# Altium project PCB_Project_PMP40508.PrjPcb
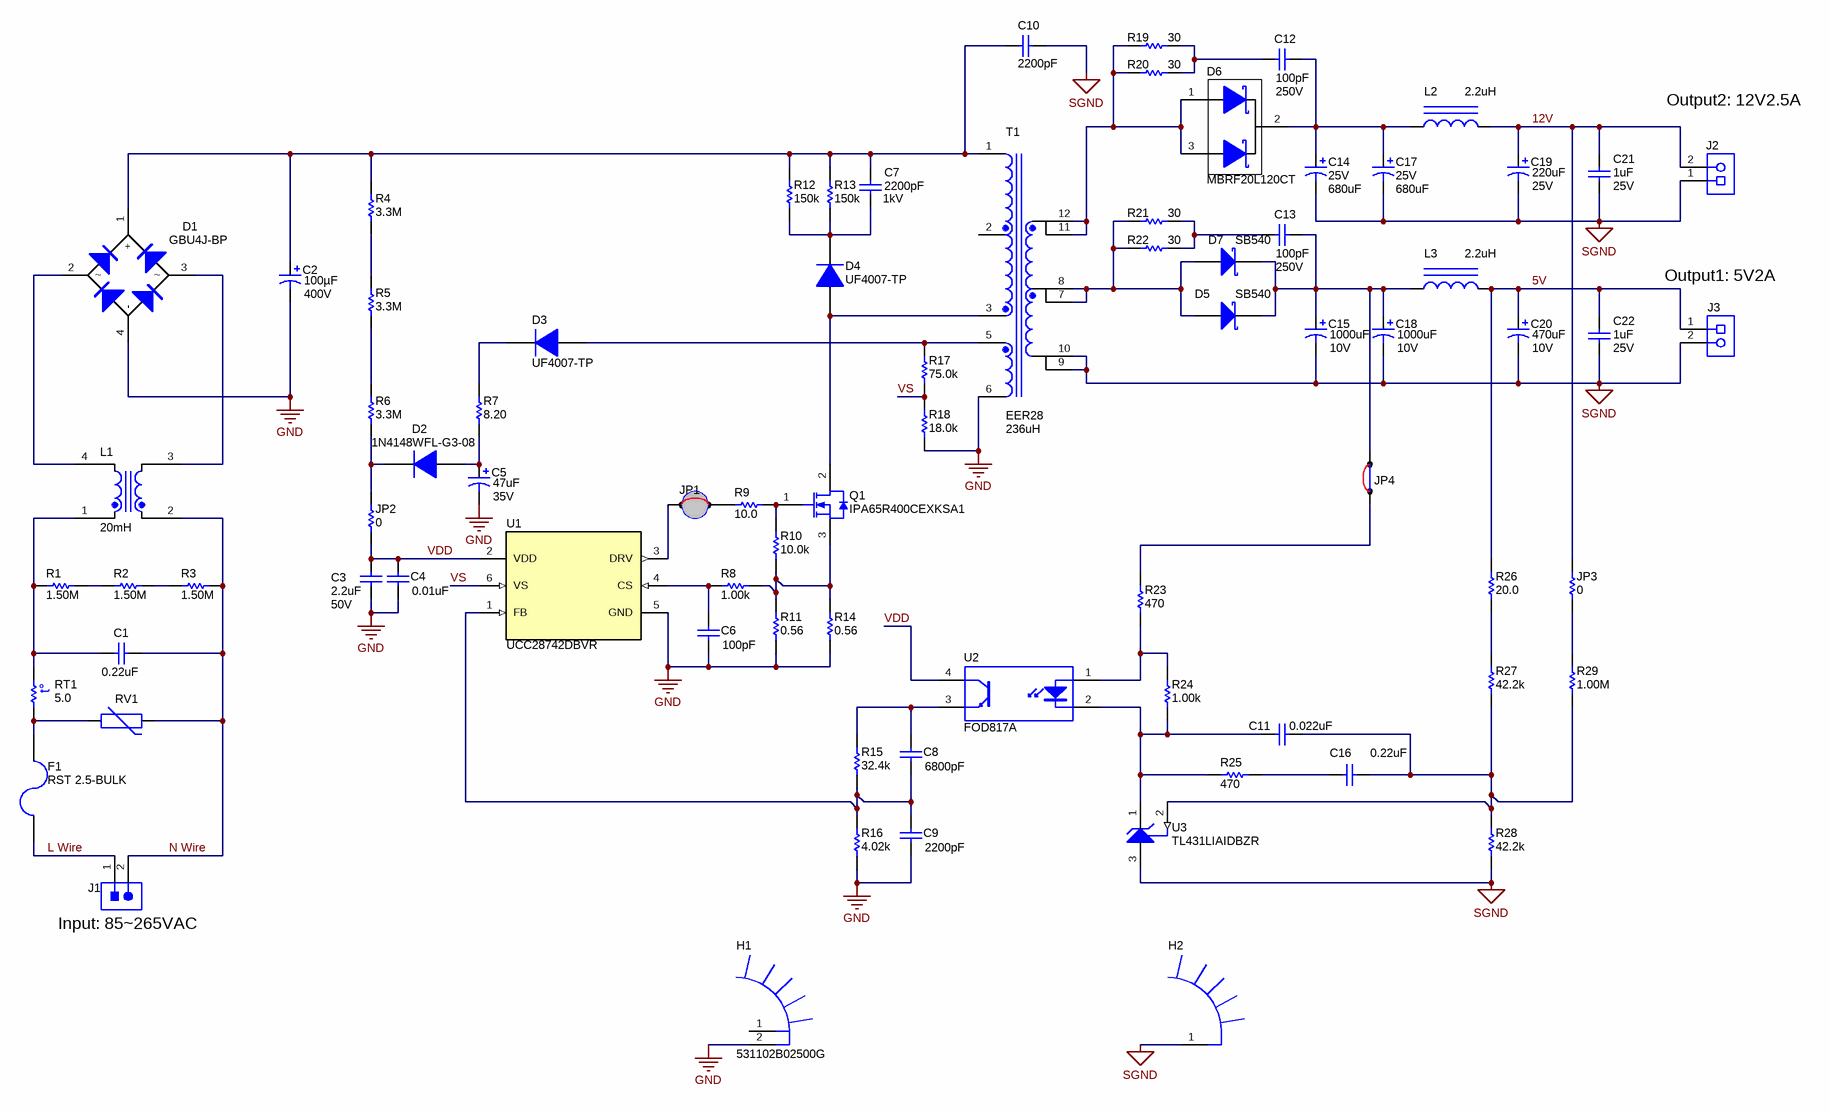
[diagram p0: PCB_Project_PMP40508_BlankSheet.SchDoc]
TID: N/A; TechSupport: http://www.ti.com/support; SCH_Rev: E1; PRJ_Title: AC input, 5V/2A and 12V/2.5A Flyback Converter; PRJ_Number: PMP40508; PRJ_Engineer: San Chen; PRJ_Customer: Public Release; PCB_Rev: E1; PCB_Layout: San Chen; CopyrightYear: 2018
1 sheet, 78 parts. Net scope: global (net labels, ports and power ports of the same name join across sheets).
Board file: PCB_Project_PMP40508_PCB.PcbDoc

## Sheet PCB_Project_PMP40508_BlankSheet.SchDoc
size 431 x 279 mm; Date: Not shown in title block; ApprovedBy: Not shown in title block; CheckedBy: Not shown in title block; Author: Not shown in title block; CompanyName: Not shown in title block; DrawnBy: San Chen; Engineer: Not shown in title block; Organization: Not shown in title block; Address1: Not shown in title block; Address2: Not shown in title block; Address3: Not shown in title block; Address4: Not shown in title block; DocumentNumber: 1; Revision: Use project parameter SCH_Rev; SheetNumber: 1; SheetTotal: 1; PageSetup: Record=PageOptions¦CenterHorizontal=True¦CenterVertical=True¦PrintScale=1.00¦XCorrection=1.00¦YCorrection=1.00¦PrintKind=0¦BorderSize=5000000¦LeftOffset=0¦BottomOffset=0¦Orientation=2¦PaperLength=1000¦PaperWidth=1000¦Scale=100¦PaperSource=15¦PrintQuality=600¦MediaType=1¦DitherType=10¦PaperKind=Letter¦PrintScaleMode=1

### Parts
C1  ValueDisplayed: 0.22uF  [WCAP-FTX2_1800x600x1150]  (hidden comment: 890324025027CS)
C2  VDC_V: 400V  ValueDisplayed: 100µF  [Chemi-Con_1800x3150]  (hidden comment: EKXG401ELL101MMN3S)
C3  VDC_V: 50V  ValueDisplayed: 2.2uF  [0805_HV]  (hidden comment: C2012X7R1H225K125AC)
C4  ValueDisplayed: 0.01uF  [0603]  (hidden comment: GRM188R71H103KA01D)
C5  VDC_V: 35V  ValueDisplayed: 47uF  [Chemi-Con_500x1100]  (hidden comment: EKMG350ELL470ME11D)
C6  ValueDisplayed: 100pF  [0603]  (hidden comment: CL10B101KB8NNNC)
C7  VDC_V: 1kV  ValueDisplayed: 2200pF  [CK45_850x500x1250]  (hidden comment: CK45-B3AD222KYNNA)
C8  ValueDisplayed: 6800pF  [0603]  (hidden comment: GRM188R71H682KA01D)
C9  ValueDisplayed: 2200pF  [0603]  (hidden comment: GRM188R71H222KA01D)
C10  ValueDisplayed: 2200pF  [C900_9x13]  (hidden comment: C921U222MVVDBA7317)
C11  ValueDisplayed: 0.022uF  [0603]  (hidden comment: GRM188R71H223KA01D)
C12  VDC_V: 250V  ValueDisplayed: 100pF  [0805_HV]  (hidden comment: GRM21A5C2E101JW01D)
C13  VDC_V: 250V  ValueDisplayed: 100pF  [0805_HV]  (hidden comment: GRM21A5C2E101JW01D)
C14  VDC_V: 25V  ValueDisplayed: 680uF  [Chemi-Con_1000x2000]  (hidden comment: EKZE250ELL681MJ20S)
C15  VDC_V: 10V  ValueDisplayed: 1000uF  [Chemi-Con_1000x1600]  (hidden comment: EKZE100ELL102MJ16S)
C16  ValueDisplayed: 0.22uF  [0603]  (hidden comment: GRM188R71E224KA88D)
C17  VDC_V: 25V  ValueDisplayed: 680uF  [Chemi-Con_1000x2000]  (hidden comment: EKZE250ELL681MJ20S)
C18  VDC_V: 10V  ValueDisplayed: 1000uF  [Chemi-Con_1000x1600]  (hidden comment: EKZE100ELL102MJ16S)
C19  VDC_V: 25V  ValueDisplayed: 220uF  [Chemi-Con_800x1150]  (hidden comment: EKZE250ELL221MHB5D)
C20  VDC_V: 10V  ValueDisplayed: 470uF  [Chemi-Con_800x1150]  (hidden comment: EKZE100ELL471MHB5D)
C21  VDC_V: 25V  ValueDisplayed: 1uF  [0805_HV]  (hidden comment: GRM216R61E105KA12D)
C22  VDC_V: 25V  ValueDisplayed: 1uF  [0805_HV]  (hidden comment: GRM216R61E105KA12D)
D1  GBU4J-BP  [GBU]
D2  1N4148WFL-G3-08  [SOD-123FL]
D3  UF4007-TP  [DO-41]
D4  UF4007-TP  [DO-41]
D5  SB540  [DO-201AD_Vert]
D6  MBRF20L120CT  [TO-220AB]
D7  SB540  [DO-201AD_Vert]
F1  RST 2.5-BULK  [FUSE_RST]
H1  531102B02500G  [531102]
H2  (no value)  [PCBComponent_1]
J1  1-1318301-2  [Amp_1-1318301-2]  (value not drawn)
J2  691214110002  [Wurth_691214110002]  (value not drawn)
J3  691214110002  [Wurth_691214110002]  (value not drawn)
JP1  923345-02-C  [923345-02-C]  (value not drawn)
JP2  ValueDisplayed: 0  [1206]  (hidden comment: RC1206JR-070RL)
JP3  ValueDisplayed: 0  [1206]  (hidden comment: RC1206JR-070RL)
JP4  923345-02-C  [923345-02-C]  (value not drawn)
L1  value 20mH  [WE-CMB_M]  (hidden comment: 744823220)
L2  ValueDisplayed: 2.2uH  [WE-TI_5075]  (hidden comment: 7447462022)
L3  ValueDisplayed: 2.2uH  [WE-TI_5075]  (hidden comment: 7447462022)
Q1  IPA65R400CEXKSA1  [TO-220FP]
R1  ValueDisplayed: 1.50M  [1206]  (hidden comment: RC1206FR-071M5L)
R2  ValueDisplayed: 1.50M  [1206]  (hidden comment: RC1206FR-071M5L)
R3  ValueDisplayed: 1.50M  [1206]  (hidden comment: RC1206FR-071M5L)
R4  ValueDisplayed: 3.3M  [1206]  (hidden comment: CRCW12063M30JNEA)
R5  ValueDisplayed: 3.3M  [1206]  (hidden comment: CRCW12063M30JNEA)
R6  ValueDisplayed: 3.3M  [1206]  (hidden comment: CRCW12063M30JNEA)
R7  ValueDisplayed: 8.20  [1206]  (hidden comment: RC1206FR-078R2L)
R8  ValueDisplayed: 1.00k  [0603]  (hidden comment: RC0603FR-071KL)
R9  ValueDisplayed: 10.0  [1206]  (hidden comment: RC1206FR-0710RL)
R10  ValueDisplayed: 10.0k  [0603]  (hidden comment: RC0603FR-0710KL)
R11  ValueDisplayed: 0.56  [1206]  (hidden comment: ERJ-8RQFR56V)
R12  ValueDisplayed: 150k  [PR01]  (hidden comment: PR01000101503JR500)
R13  ValueDisplayed: 150k  [PR01]  (hidden comment: PR01000101503JR500)
R14  ValueDisplayed: 0.56  [1206]  (hidden comment: ERJ-8RQFR56V)
R15  ValueDisplayed: 32.4k  [0603]  (hidden comment: RC0603FR-0732K4L)
R16  ValueDisplayed: 4.02k  [0603]  (hidden comment: RC0603FR-074K02L)
R17  ValueDisplayed: 75.0k  [0805_HV]  (hidden comment: ERJ-6ENF7502V)
R18  ValueDisplayed: 18.0k  [0603]  (hidden comment: RC0603FR-0718KL)
R19  ValueDisplayed: 30  [1206]  (hidden comment: CRCW120630R0JNEA)
R20  ValueDisplayed: 30  [1206]  (hidden comment: CRCW120630R0JNEA)
R21  ValueDisplayed: 30  [1206]  (hidden comment: CRCW120630R0JNEA)
R22  ValueDisplayed: 30  [1206]  (hidden comment: CRCW120630R0JNEA)
R23  ValueDisplayed: 470  [0603]  (hidden comment: RC0603FR-07470RL)
R24  ValueDisplayed: 1.00k  [0603]  (hidden comment: RC0603FR-071KL)
R25  ValueDisplayed: 470  [0603]  (hidden comment: RC0603FR-07470RL)
R26  ValueDisplayed: 20.0  [0603]  (hidden comment: RC0603FR-0720RL)
R27  ValueDisplayed: 42.2k  [0603]  (hidden comment: RC0603FR-0742K2L)
R28  ValueDisplayed: 42.2k  [0603]  (hidden comment: RC0603FR-0742K2L)
R29  ValueDisplayed: 1.00M  [0603]  (hidden comment: RC0603FR-071ML)
RT1  value 5.0  [S235]  (hidden comment: B57235S0509M000)
RV1  B72210S2271K101  [TDK_B72210S2271K101]  (value not drawn)
T1  value 236uH  ValueDisplayed: EER28  [PCBComponent_1]  (hidden comment: YXS60989T)
U1  UCC28742DBVR  [DBV0006A_N]
U2  FOD817A  [DIP-4]
U3  TL431LIAIDBZR  [DBZ0003A_N]

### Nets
GND: C2.2(-) C3.2 C4.2 C5.2(-) C6.2 C9.2 D1.4(-) H1.2 R11.1 R14.1 R16.1 R18.1 T1.6 U1.5(GND)
SGND: C10.1 C14.2(-) C15.2(-) C17.2(-) C18.2(-) C19.2(-) C20.2(-) C21.2 C22.2 H2.1 J2.1 J3.2 R28.1 T1.9 T1.10 U3.3(ANODE)
5V: C20.1(+) C22.1 J3.1 L3.2 R26.2
12V: C19.1(+) C21.1 J2.2 JP3.2 L2.2
L Wire: F1.2 J1.1
N Wire: C1.1 J1.2 L1.2 R3.2 RV1.2
VDD: C3.1 C4.1 JP2.1 U1.2(VDD) U2.4(C)
VS: R17.1 R18.2 U1.6(VS)
NetC1_2: C1.2 L1.1 R1.1 RT1.2
NetC2_1: C2.1(+) C7.1 C10.2 D1.1(+) R4.2 R12.1 R13.1 T1.1
NetC5_1: C5.1(+) D2.2(A) R7.1
NetC6_1: C6.1 R8.1 U1.4(CS)
NetC7_2: C7.2 D4.1(K) R12.2 R13.2
NetC8_1: C8.1 R15.2 U2.3(E)
NetC8_2: C8.2 C9.1 R15.1 R16.2 U1.1(FB)
NetC11_1: C11.1 C16.1 R27.1 R28.2 R29.1 U3.2(REF)
NetC11_2: C11.2 R24.1 R25.2 U2.2(K) U3.1(CATHODE)
NetC12_1: C12.1 C14.1(+) C17.1(+) D6.2(K) L2.1
NetC12_2: C12.2 R19.2 R20.2
NetC13_1: C13.1 C15.1(+) C18.1(+) D5.1(K) D7.1(K) JP4.2 L3.1
NetC13_2: C13.2 R21.2 R22.2
NetC16_2: C16.2 R25.1
NetD1_2: D1.2 L1.4
NetD1_3: D1.3 L1.3
NetD2_1: D2.1(K) JP2.2 R6.1
NetD3_1: D3.1(K) R7.2
NetD3_2: D3.2(A) R17.2 T1.5
NetD4_2: D4.2(A) Q1.2(D) T1.3
NetD5_2: D5.2(A) D7.2(A) R21.1 R22.1 T1.7 T1.8
NetD6_1: D6.1(A) D6.3(A) R19.1 R20.1 T1.11 T1.12
NetF1_1: F1.1 RT1.1 RV1.1
NetJP1_1: JP1.1 U1.3(DRV)
NetJP1_2: JP1.2 R9.1
NetJP3_1: JP3.1 R29.2
NetJP4_1: JP4.1 R23.2
NetQ1_1: Q1.1(G) R9.2 R10.2
NetQ1_3: Q1.3(S) R8.2 R10.1 R11.2 R14.2
NetR1_2: R1.2 R2.1
NetR2_2: R2.2 R3.1
NetR4_1: R4.1 R5.2
NetR5_1: R5.1 R6.2
NetR23_1: R23.1 R24.2 U2.1(A)
NetR26_1: R26.1 R27.2

Not connected (* = marked no-connect by the designer): H1 1; T1 2

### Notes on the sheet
- Output2: 12V2.5A
- (near J3) Output1: 5V2A
- (near J1) Input: 85|65VAC

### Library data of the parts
C1 = CMP-0012315-3: CAP, Film, 0.22 uF, 275 V, +/- 10%, TH; Manufacturer: Wurth Elektronik; TaMin_C: -40°C; Polarized: N; Value1: Unknown; Value: 0.22uF; TaMax_C: 105°C; Cap_Case: 18x11.5x6mm; Value2: 275V; CompType: Capacitor; Cap_F: 220nF; AEC Category: Q200
C2 = CMP-0074694-1: CAP, AL, 100 µF, 400 V, +/- 20%, TH; Manufacturer: Chemi-Con; TaMin_C: -40°C; Polarized: Y; SizeAreaWB_mm2: 400.0; U/M: EA; Value: 100uF; TaMax_C: 105°C; SizeZ_mm: 33.0; SizeX_mm: 18.0; Cap_Case: 18x31.5; SizeArea_mm2: 324.0; CompType: Capacitor; AEC Qualified: N; IRMS_A: 1.72A; AEC Category: Q200
C3 = CMP-0007877-2: CAP, CERM, 2.2 uF, 50 V, +/- 10%, X7R, 0805; Manufacturer: TDK; TaMin_C: -55°C; ESR_ohm: 3.66m; Polarized: N; SizeAreaWB_mm2: 6.75; Value1: 0.00366 ohm; U/M: EA; Value: 2.2uF; TaMax_C: 125°C; SizeZ_mm: 1.45; SizeX_mm: 2; SizeY_mm: 1.25; Cap_Case: 0805; SizeArea_mm2: 2.5; Cap_F: 2.2µF; IRMS_A: 3.41207A; AEC Category: Q200
C4 = CMP-0007433-4: CAP, CERM, 0.01 uF, 50 V, +/- 10%, X7R, 0603; Manufacturer: MuRata; TaMin_C: -55°C; Polarized: N; SizeAreaWB_mm2: 4.68; Value1: Unknown; U/M: EA; Value: 0.01uF; TaMax_C: 125°C; SizeZ_mm: 1; SizeX_mm: 1.6; SizeY_mm: 0.8; Value2: 50V; SizeArea_mm2: 1.28; CompType: Capacitor; Cap_F: 10nF; AEC Category: Q200
C5 = CMP-0010368-2: CAP, AL, 47 uF, 35 V, +/- 20%, TH; Manufacturer: Chemi-Con; TaMin_C: -55°C; Polarized: Y; SizeAreaWB_mm2: 49; Value1: Unknown; U/M: EA; Value: 47uF; TaMax_C: 105°C; SizeZ_mm: 12.5; SizeX_mm: 5; Cap_Case: 5x11mm; SizeArea_mm2: 25; CompType: Capacitor; AEC Qualified: N; Cap_F: 47µF; IRMS_A: 90mA; AEC Category: Q200
C6 = CMP-0083857-1: CAP, CERM, 100 pF, 50 V,+/- 10%, X7R, 0603; Manufacturer: Samsung Electro-Mechanics; TaMin_C: -55°C; Polarized: N; SizeAreaWB_mm2: 4.68; U/M: EA; Value: 100pF; TaMax_C: 125°C; SizeZ_mm: 1; SizeX_mm: 1.6; SizeY_mm: 0.8; Value2: 50V; SizeArea_mm2: 1.28; CompType: Capacitor; AEC Category: Q200
C7 = CMP-0009598-2: CAP, CERM, 2200 pF, 1000 V, +/- 10%, B, D8.5xT5mm; Manufacturer: TDK; TaMin_C: -25°C; Polarized: N; SizeAreaWB_mm2: 73.5; Value1: Unknown; U/M: EA; Value: 2200pF; TaMax_C: 105°C; SizeZ_mm: 12.5; SizeX_mm: 8.5; SizeY_mm: 5; Cap_Case: 8.5x5x12.5mm; Value2: 1000V; SizeArea_mm2: 42.5; CompType: Capacitor; Cap_F: 2.2nF; AEC Category: Q200
C8 = CMP-0007462-4: CAP, CERM, 6800 pF, 50 V, +/- 10%, X7R, 0603; Manufacturer: MuRata; TaMin_C: -55°C; Polarized: N; SizeAreaWB_mm2: 4.68; Value1: Unknown; U/M: EA; Value: 6800pF; TaMax_C: 125°C; SizeZ_mm: 1; SizeX_mm: 1.6; SizeY_mm: 0.8; Value2: 50V; SizeArea_mm2: 1.28; CompType: Capacitor; Cap_F: 6.8nF; AEC Category: Q200
C9 = CMP-0007443-4: CAP, CERM, 2200 pF, 50 V, +/- 10%, X7R, 0603; Manufacturer: MuRata; TaMin_C: -55°C; Polarized: N; SizeAreaWB_mm2: 4.68; Value1: Unknown; U/M: EA; Value: 2200pF; TaMax_C: 125°C; SizeZ_mm: 1; SizeX_mm: 1.6; SizeY_mm: 0.8; Value2: 50V; SizeArea_mm2: 1.28; CompType: Capacitor; Cap_F: 2.2nF; AEC Category: Q200
C10 = CMP-0078358-1: CAP, CERM, 2200 pF, X1 400 VAC/Y1 400 VAC, +/- 20%, Y5V, D9xL13mm; Manufacturer: Kemet; Cap_F: 2.2nF; SizeAreaWB_mm2: 121; VAC_X: 400V; SizeArea_mm2: 81; AEC Qualified: N; AEC Category: Q200; Value: 2200pF; TaMax_C: 125°C; SizeZ_mm: 13; TaMin_C: -40°C; SizeY_mm: 9; U/M: EA; AC_Safety: X1Y1; Cap_Case: 9x13mm
C11 = CMP-0007444-4: CAP, CERM, 0.022 uF, 50 V, +/- 10%, X7R, 0603; Manufacturer: MuRata; TaMin_C: -55°C; Polarized: N; SizeAreaWB_mm2: 4.68; Value1: Unknown; U/M: EA; TaMax_C: 125°C; SizeZ_mm: 1; SizeX_mm: 1.6; SizeY_mm: 0.8; Value2: 50V; SizeArea_mm2: 1.28; CompType: Capacitor; Cap_F: 22nF; AEC Category: Q200
C12 C13 = CMP-0008236-2: CAP, CERM, 100 pF, 250 V, +/- 5%, C0G/NP0, 0805; Manufacturer: MuRata; TaMin_C: -55°C; Polarized: N; SizeAreaWB_mm2: 6.75; Value1: Unknown; U/M: EA; Value: 100pF; TaMax_C: 125°C; SizeZ_mm: 1.45; SizeX_mm: 2; SizeY_mm: 1.25; Cap_Case: 0805; SizeArea_mm2: 2.5; AEC Category: Q200
C14 C17 = CMP-0010412-1: CAP, AL, 680 uF, 25 V, +/- 20%, TH; Manufacturer: Chemi-Con; TaMin_C: -40°C; Polarized: Y; SizeAreaWB_mm2: 144; Value1: Unknown; U/M: EA; Value: 680uF; TaMax_C: 105°C; SizeZ_mm: 21.5; SizeX_mm: 10; Cap_Case: 10x20; SizeArea_mm2: 100; CompType: Capacitor; AEC Qualified: N; Cap_F: 680µF; IRMS_A: 1.82A; AEC Category: Q200
C15 C18 = CMP-0010377-1: CAP, AL, 1000 uF, 10 V, +/- 20%, TH; Manufacturer: Chemi-Con; TaMin_C: -40°C; Polarized: Y; SizeAreaWB_mm2: 144; Value1: Unknown; U/M: EA; Value: 1000uF; TaMax_C: 105°C; SizeZ_mm: 17.5; SizeX_mm: 10; Cap_Case: 10x16mm; SizeArea_mm2: 100; CompType: Capacitor; AEC Qualified: N; Cap_F: 1mF; IRMS_A: 1.43A; AEC Category: Q200
C16 = CMP-0007415-4: CAP, CERM, 0.22 uF, 25 V, +/- 10%, X7R, 0603; Manufacturer: MuRata; TaMin_C: -55°C; Polarized: N; SizeAreaWB_mm2: 4.68; Value1: Unknown; U/M: EA; Value: 0.22uF; TaMax_C: 125°C; SizeZ_mm: 1; SizeX_mm: 1.6; SizeY_mm: 0.8; Value2: 25V; SizeArea_mm2: 1.28; CompType: Capacitor; Cap_F: 220nF; AEC Category: Q200
C19 = CMP-0010404-1: CAP, AL, 220 uF, 25 V, +/- 20%, TH; Manufacturer: Chemi-Con; TaMin_C: -40°C; Polarized: Y; SizeAreaWB_mm2: 100; Value1: Unknown; U/M: EA; Value: 220uF; TaMax_C: 105°C; SizeZ_mm: 13; SizeX_mm: 8; Cap_Case: 8x11.5; SizeArea_mm2: 64; CompType: Capacitor; AEC Qualified: N; Cap_F: 220µF; IRMS_A: 7.6dA; AEC Category: Q200
C20 = CMP-0010383-1: CAP, AL, 470 uF, 10 V, +/- 20%, TH; Manufacturer: Chemi-Con; TaMin_C: -40°C; Polarized: Y; SizeAreaWB_mm2: 100; Value1: Unknown; U/M: EA; Value: 470uF; TaMax_C: 105°C; SizeZ_mm: 13; SizeX_mm: 8; Cap_Case: 8x11.5; SizeArea_mm2: 64; CompType: Capacitor; AEC Qualified: N; Cap_F: 470µF; IRMS_A: 7.6dA; AEC Category: Q200
C21 C22 = CMP-0008136-2: CAP, CERM, 1 uF, 25 V, +/- 10%, X5R, 0805; Manufacturer: MuRata; TaMin_C: -55°C; ESR_ohm: 9m; Polarized: N; SizeAreaWB_mm2: 6.75; Value1: 0.009 ohm; U/M: EA; Value: 1uF; TaMax_C: 85°C; SizeZ_mm: 1.45; SizeX_mm: 2; SizeY_mm: 1.25; Cap_Case: 0805; SizeArea_mm2: 2.5; Cap_F: 1µF; AEC Category: Q200
D1 = CMP-0029241-3: Diode, P-N-Bridge, 600 V, 4 A, TH; Manufacturer: Micro Commercial Components; Green_Lifecycle: Not Set; Green_REACh: Incomplete; Io_A: 4A; AEC Category: Q101; SizeX_mm: 22.05; SizeY_mm: 3.43; Value2: 1V; RJC_CperW: 2.2; SizeAreaWB_mm2: 130.5915; Vr_V: 600V; SizeArea_mm2: 75.6315; SizeZ_mm: 21.55; TJmax_C: 150°C; Value: 600V
D2 = CMP-0076920-2: Diode, Switching, 100 V, 0.15 A, SOD-123FL; Manufacturer: Vishay-Semiconductor; Vr_V: 100V; Green_Lifecycle: Not Set; SizeY_mm: 1.65; SizeAreaWB_mm2: 12.19; Io_A: 1.5dA; SizeZ_mm: 0.98; Green_REACh: Incomplete; Value1: 0.15A; Vf_V: 1.2V; SizeArea_mm2: 5.94; SizeX_mm: 3.6; Value: 100V; TJmax_C: 150°C; AEC Category: Q101
D3 D4 = CMP-0077016-2: Diode, Ultrafast, 1000 V, 1 A, TH; Manufacturer: Micro Commercial Components; SizeX_mm: 7.2; Value2: 1.7V; SizeY_mm: 2.72; TJmax_C: 125°C; Io_A: 1A; Vr_V: 1kV; AEC Category: Q101; Value: 1000V; SizeAreaWB_mm2: 43.424; SizeZ_mm: 23.4; SizeArea_mm2: 19.584; Green_REACh: Incomplete; Green_Lifecycle: Not Set
D5 D7 = CMP-0076935-2: Diode, Schottky, 40 V, 5 A, TH; Manufacturer: ON Semiconductor / Fairchild; Element Configuration: Single; Max Surge Current: 150A; Max Reverse Leakage Current: 500uA; Forward Current: 5A; Max Repetitive Reverse Voltage (Vrrm): 40V; Forward Voltage: 550mV; Max Forward Surge Current (Ifsm): 100A; Polarity: Standard
D6 = CMP-0028764-3: Diode, Schottky, 120 V, 20 A, TH; Manufacturer: Taiwan Semiconductor
F1 = CMP-0081660-1: Fuse, 2.5 A, 250 VAC, TH; Manufacturer: Bel Fuse; TaMin_C: -55°C; Irating_A: 2.5A; SizeAreaWB_mm2: 62.1; VAC_V: 250V; TaMax_C: 125°C; Fuse Speed: Slow; SizeZ_mm: 7.9; SizeX_mm: 8.35; SizeY_mm: 4; SizeArea_mm2: 33.4; Fuse Technology: Board Mount; Rtyp_Ohm: 0.022; MeltingTyp: 43
H1 = CMP-0004063-1: Manufacturer: Aavid; CompType: Heat Sink
H2 = HeatSink_2: Manufacturer: Aavid; Key: 531102B02500G
J1 = CMP-0054833-1: Polarized Header, 7.92 mm, 2x1, Tin, TH; Manufacturer: TE Connectivity; CNHeader: FALSE; Current_A: 7.5A; Green_Lifecycle: Not Set; Shrouded: N; Gender: Male; Green_REACh: Incomplete; Voltage_V: 250V; CompType: Connector; Row_Count: 1; Pitch_mm: 7.92; Cert_UL: Y
J2 J3 = CMP-0054825-2: Terminal Block, 3.5mm, 2x1, Tin, TH; Manufacturer: Wurth Elektronik; Pitch_mm: 3.5; CT: TRUE; CNHeader: FALSE; Voltage_V: 300V; Gender: Female; Cert_UL: Y; Row_Count: 1; Current_A: 10A
JP1 JP4 = CMP-0055439-1: Jumper Wire, 200mil spacing, Red, pkg of 200; Manufacturer: 3M; CNHeader: FALSE; Green_Lifecycle: Active; Green_REACh: Passed
JP2 JP3 = CMP-0018759-2: RES, 0, 5%, 0.25 W, 1206; Manufacturer: Yageo America; Power_W: 250mW; TempCo: 200 ppm/C; Value_Code: 0000; U/M: EA; Value: 0; EIA_Code: E24; SizeX_mm: 3.2; SizeY_mm: 1.6; SizeZ_mm: 1.35; Value2: 0.25W; SizeArea_mm2: 5.12; VDC_V: 200V; AEC Category: Q200
L1 = CMP-0013122-2: Coupled inductor, 20 mH, 1.5 A, 0.27 ohm, TH; Manufacturer: Wurth Elektronik; SizeAreaWB_mm2: 513; DCR_ohm: 2.7d; SizeZ_mm: 26.5; SizeX_mm: 25; SizeY_mm: 17; SizeArea_mm2: 425
L2 L3 = CMP-0064180-1: Inductor, Unshielded Drum Core, Ferrite, 2.2 uH, 4.3 A, 0.01 ohm, TH; Manufacturer: Wurth Elektronik; Isat: 4.3A @ 10% inductance drop; Irms: 6.3A @ 40C rise; Green_Lifecycle: Active; SizeAreaWB_mm2: 64; DCR_ohm: 0.01; Green_REACh: Passed; Value: 2.2uH; Imax_A: 4.3A; SizeZ_mm: 8.5; SizeX_mm: 6; SizeArea_mm2: 36; Ind_H: 2.2µH; AEC Category: Q200
Q1 = CMP-0001231-4: MOSFET, N-CH, 650 V, 15.1 A, TO-220FP; Manufacturer: Infineon; VdsMax_V: 650V; Rds On Max: 400mR; Input Capacitance: 710pF; Max Power Dissipation: 31W
R1-R3 = CMP-0018015-2: RES, 1.50 M, 1%, 0.25 W, 1206; Manufacturer: Yageo America; Power_W: 250mW; TempCo: 100 ppm/C; Value_Code: 1M50; U/M: EA; Value: 1.50Meg; EIA_Code: E96; Res_ohm: 1.5M; SizeX_mm: 3.2; SizeY_mm: 1.6; SizeZ_mm: 1.35; Value2: 0.25W; SizeArea_mm2: 5.12; VDC_V: 200V; AEC Category: Q200
R4-R6 = CMP-0018673-3: RES, 3.3 M, 5%, 0.25 W, AEC-Q200 Grade 0, 1206; Manufacturer: Vishay-Dale; Power_W: 250mW; TempCo: 200 ppm/C; Value_Code: 3M30; Value: 3.3Meg; EIA_Code: E24; SizeX_mm: 3.2; SizeY_mm: 1.6; SizeZ_mm: 1.35; Value2: 0.25W; SizeArea_mm2: 5.12; AEC Qualified: Y; VDC_V: 200V; AEC Category: Q200; AEC Grade: 0
R7 = CMP-0018523-2: RES, 8.20, 1%, 0.25 W, 1206; Manufacturer: Yageo America; Power_W: 250mW; TempCo: 200 ppm/C; Value_Code: 8R20; U/M: EA; Value: 8.20; Res_ohm: 8.2; SizeX_mm: 3.2; SizeY_mm: 1.6; SizeZ_mm: 1.35; Value2: 0.25W; SizeArea_mm2: 5.12; VDC_V: 200V; AEC Category: Q200
R8 R24 = CMP-0022895-5: RES, 1.00 k, 1%, 0.1 W, 0603; Manufacturer: Yageo; Power_W: 100mW; TempCo: 100 ppm/C; Value_Code: 1k00; Value: 1.00k; EIA_Code: E96; Res_ohm: 1k; SizeX_mm: 1.6; SizeY_mm: 0.8; SizeZ_mm: 1; Value2: 0.1W; SizeArea_mm2: 1.28; AEC Qualified: N; VDC_V: 75V; AEC Category: Q200; SizeAreaWB_mm2: 4.68
R9 = CMP-0017851-2: RES, 10.0, 1%, 0.25 W, 1206; Manufacturer: Yageo America; Power_W: 250mW; TempCo: 200 ppm/C; Value_Code: 10R0; U/M: EA; Value: 10.0; EIA_Code: E96; Res_ohm: 10; SizeX_mm: 3.2; SizeY_mm: 1.6; SizeZ_mm: 1.35; Value2: 0.25W; SizeArea_mm2: 5.12; VDC_V: 200V; AEC Category: Q200
R10 = CMP-0022746-5: RES, 10.0 k, 1%, 0.1 W, 0603; Manufacturer: Yageo; Power_W: 100mW; TempCo: 100 ppm/C; Value_Code: 10k0; Value: 10.0k; EIA_Code: E96; Res_ohm: 10k; SizeX_mm: 1.6; SizeY_mm: 0.8; SizeZ_mm: 1; Value2: 0.1W; SizeArea_mm2: 1.28; AEC Qualified: N; VDC_V: 75V; AEC Category: Q200; SizeAreaWB_mm2: 4.68
R11 R14 = CMP-0017792-3: RES, 0.56, 1%, 0.25 W, AEC-Q200 Grade 0, 1206; Manufacturer: Panasonic; Power_W: 250mW; TempCo: 250 ppm/C; Value_Code: R560; Value: 0.56; EIA_Code: E96; Res_ohm: 5.6d; SizeX_mm: 3.2; SizeY_mm: 1.6; SizeZ_mm: 1.35; Value2: 0.25W; SizeArea_mm2: 5.12; AEC Qualified: Y; AEC Category: Q200; AEC Grade: 0; SizeAreaWB_mm2: 10.92
R12 R13 = CMP-0014328-2: RES, 150 k, 5%, 1 W, AEC-Q200 Grade 0, D2.5xL6.5mm; Manufacturer: Vishay-Bccomponents; Power_W: 1W; TempCo: 250 ppm/C; U/M: EA; Value: 150k; EIA_Code: E24; AEC Qualified: Y; VDC_V: 350V; AEC Grade: 0; AEC Category: Q200
R15 = CMP-0023030-5: RES, 32.4 k, 1%, 0.1 W, 0603; Manufacturer: Yageo; Power_W: 100mW; TempCo: 100 ppm/C; Value_Code: 32k4; Value: 32.4k; EIA_Code: E96; SizeX_mm: 1.6; SizeY_mm: 0.8; SizeZ_mm: 1; Value2: 0.1W; SizeArea_mm2: 1.28; AEC Qualified: N; VDC_V: 75V; AEC Category: Q200; SizeAreaWB_mm2: 4.68
R16 = CMP-0023144-5: RES, 4.02 k, 1%, 0.1 W, 0603; Manufacturer: Yageo; Power_W: 100mW; TempCo: 100 ppm/C; Value_Code: 4k02; Value: 4.02k; EIA_Code: E96; SizeX_mm: 1.6; SizeY_mm: 0.8; SizeZ_mm: 1; Value2: 0.1W; SizeArea_mm2: 1.28; AEC Qualified: N; VDC_V: 75V; AEC Category: Q200; SizeAreaWB_mm2: 4.68
R17 = CMP-0021786-3: RES, 75.0 k, 1%, 0.125 W, AEC-Q200 Grade 0, 0805; Manufacturer: Panasonic; Power_W: 125mW; TempCo: 100 ppm/C; Value_Code: 75k0; Value: 75.0k; EIA_Code: E96; Res_ohm: 75k; SizeX_mm: 2; SizeY_mm: 1.25; SizeZ_mm: 1.45; Value2: 0.125W; SizeArea_mm2: 2.5; AEC Qualified: Y; AEC Category: Q200; AEC Grade: 0; SizeAreaWB_mm2: 6.75
R18 = CMP-0022852-5: RES, 18.0 k, 1%, 0.1 W, 0603; Manufacturer: Yageo; Power_W: 100mW; TempCo: 100 ppm/C; Value_Code: 18k0; Value: 18.0k; Res_ohm: 18k; SizeX_mm: 1.6; SizeY_mm: 0.8; SizeZ_mm: 1; Value2: 0.1W; SizeArea_mm2: 1.28; AEC Qualified: N; VDC_V: 75V; AEC Category: Q200; SizeAreaWB_mm2: 4.68
R19-R22 = CMP-0018655-3: RES, 30, 5%, 0.25 W, AEC-Q200 Grade 0, 1206; Manufacturer: Vishay-Dale; Power_W: 250mW; TempCo: 200 ppm/C; Value_Code: 30R0; Value: 30; EIA_Code: E24; SizeX_mm: 3.2; SizeY_mm: 1.6; SizeZ_mm: 1.35; Value2: 0.25W; SizeArea_mm2: 5.12; AEC Qualified: Y; VDC_V: 200V; AEC Category: Q200; AEC Grade: 0
R23 R25 = CMP-0023129-5: RES, 470, 1%, 0.1 W, 0603; Manufacturer: Yageo; Power_W: 100mW; TempCo: 100 ppm/C; Value_Code: 470R; Value: 470; SizeX_mm: 1.6; SizeY_mm: 0.8; SizeZ_mm: 1; Value2: 0.1W; SizeArea_mm2: 1.28; AEC Qualified: N; VDC_V: 75V; AEC Category: Q200; SizeAreaWB_mm2: 4.68
R26 = CMP-0022908-4: RES, 20.0, 1%, 0.1 W, 0603; Manufacturer: Yageo; Power_W: 100mW; TempCo: 100 ppm/C; Value_Code: 20R0; Value: 20.0; EIA_Code: E96; Res_ohm: 20; SizeX_mm: 1.6; SizeY_mm: 0.8; SizeZ_mm: 1; Value2: 0.1W; SizeArea_mm2: 1.28; AEC Qualified: N; VDC_V: 75V; AEC Category: Q200; SizeAreaWB_mm2: 4.68
R27 R28 = CMP-0023106-5: RES, 42.2 k, 1%, 0.1 W, 0603; Manufacturer: Yageo; Power_W: 100mW; TempCo: 100 ppm/C; Value_Code: 42k2; Value: 42.2k; EIA_Code: E96; SizeX_mm: 1.6; SizeY_mm: 0.8; SizeZ_mm: 1; Value2: 0.1W; SizeArea_mm2: 1.28; AEC Qualified: N; VDC_V: 75V; AEC Category: Q200; SizeAreaWB_mm2: 4.68
R29 = CMP-0022899-4: RES, 1.00 M, 1%, 0.1 W, 0603; Manufacturer: Yageo; Power_W: 100mW; TempCo: 100 ppm/C; Value_Code: 1M00; Value: 1.00Meg; EIA_Code: E96; Res_ohm: 1M; SizeX_mm: 1.6; SizeY_mm: 0.8; SizeZ_mm: 1; Value2: 0.1W; SizeArea_mm2: 1.28; AEC Qualified: N; VDC_V: 75V; AEC Category: Q200; SizeAreaWB_mm2: 4.68
RT1 = CMP-0002553-2: Thermistor NTC, 5.0 ohm, 20%, D9.5xT6mm; Manufacturer: TDK EPCOS; Lead Length: 25mm; Approvals: UL
RV1 = CMP-0082388-2: Varistor, 430V, 3.5kA, 10mm Disc, TH; Manufacturer: TDK; SizeAreaWB_mm2: 103.6; SizeArea_mm2: 64.8; SizeX_mm: 12; SizeZ_mm: 14.5; SizeY_mm: 5.4
T1 = RLTI-1168: Transformer, 236 uH, TH; Manufacturer: Yaxin Electronics; SymbolCreator: Altium; DCR_ohm: 0.24; Rsec1_ohm: 0.006; Rsec2_ohm: 0.01; SizeX_mm: 30; SizeY_mm: 31.5; SizeZ_mm: 25
U1 = CMP-0078369-2: High-Efficiency Low-Cost Flyback Controller with Secondary-Side Regulation, DBV0006A (SOT-23-6); Manufacturer: Texas Instruments; SizeZ_mm: 1.45; SizeX_mm: 2.8; SizeY_mm: 2.9; AEC Category: Q200; AEC Qualified: N; SizeArea_mm2: 8.12; CompType: IC; SizeAreaWB_mm2: 14.82
U2 = CMP-0006173-3: Optocoupler, 5 kV, 80-160% CTR, TH; Manufacturer: Fairchild Semiconductor; CTR (Max): 160%; SizeAreaWB_mm2: 71.064; CTR (Min): 80%; SizeZ_mm: 5; SizeX_mm: 8.8; SizeY_mm: 4.58; SizeArea_mm2: 40.304; Voltage_Isolation_Vrms: 5kV
U3 = CMP-0084729-1: Programmable Shunt Regulator with Optimized Reference Current, DBZ0003A (SOT-23-3); Manufacturer: Texas Instruments; SizeY_mm: 3; SizeZ_mm: 1.12; SizeX_mm: 2.5; SizeAreaWB_mm2: 14; CompType: IC; AEC Qualified: N; AEC Category: Q200; SizeArea_mm2: 7.5

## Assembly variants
001: not fitted C8 C17 C18 JP3 R19 R29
